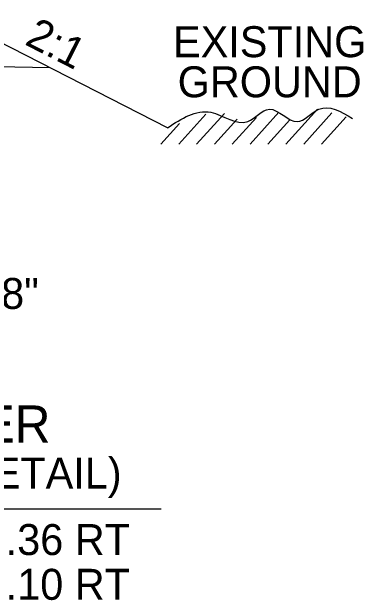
# Model space of a CAD drawing. Extents: x 1553884 to 1554215, y 810431 to 810779.
# Drawn here: x 1554057.23 to 1554068.58, y 810651.68 to 810670.68 of the extents above; entities that cross this region are included whole.
import ezdxf

# ---------------------------------------------------------------- set-up
doc = ezdxf.new("R2010")
doc.units = 0
for name, color, linetype in [('Old_Level_1', 7, 'Continuous'), ('Prop CMT Steel Beam Girder', 7, 'Continuous'), ('Typical Arrow Superelevation CELL', 7, 'Continuous'), ('Typical Shoulder Slope CELL', 7, 'Continuous')]:
    doc.layers.add(name, color=color, linetype=linetype)

msp = doc.modelspace()

# ---------------------------------------------------------------- linework, layer by layer
at = {"layer": 'Old_Level_1'}
for p, q in [((1554062.264, 810666.94), (1554054.916, 810670.684)), ((1554058.463, 810668.877), (1554036.949, 810669.189))]:
    msp.add_line(p, q, dxfattribs=at)
at = {"layer": 'Typical Arrow Superelevation CELL'}
msp.add_line((1554034.791, 810654.636), (1554062.057, 810654.636), dxfattribs=at)
at = {"layer": 'Typical Shoulder Slope CELL'}
for p, q in [((1554067.103, 810667.545), (1554066.082, 810666.41)), ((1554063.5, 810667.382), (1554062.626, 810666.41)), ((1554064.096, 810667.403), (1554063.202, 810666.41)), ((1554065.13, 810667.272), (1554064.354, 810666.41)), ((1554065.855, 810667.438), (1554064.93, 810666.41)), ((1554067.569, 810667.422), (1554066.658, 810666.41)), ((1554068.031, 810667.296), (1554067.234, 810666.41)), ((1554062.651, 810667.078), (1554062.05, 810666.41)), ((1554064.506, 810667.219), (1554063.778, 810666.41)), ((1554066.216, 810667.199), (1554065.506, 810666.41))]:
    msp.add_line(p, q, dxfattribs=at)
msp.add_spline([(1554062.264, 810666.94), (1554063.659, 810667.438), (1554064.854, 810667.139), (1554065.551, 810667.538), (1554066.447, 810667.139), (1554067.144, 810667.538), (1554068.24, 810667.239)], degree=3, dxfattribs=at)

# ---------------------------------------------------------------- texts
at = {"layer": 'Old_Level_1'}
msp.add_text('2:1', height=1, rotation=333, dxfattribs=at).set_placement((1554057.616, 810669.644))
for s, height, p in [('WIDTH VARIES 1\'-8" TO 2\'-8"', 1, (1554040.151, 810661.09)), ('SHOULDER BERM GUTTER', 1.2, (1554037.442, 810656.774))]:
    msp.add_text(s, height=height, dxfattribs=at).set_placement(p)
at = {"layer": 'Prop CMT Steel Beam Girder'}
for s, p in [('(NOTE: SCALE ENLARGED FOR DETAIL)', (1554035.07, 810655.291)), ('-L- STA 18+30.00 TO -L- STA 18+42.36 RT', (1554035.109, 810653.144)), ('-L- STA 21+28.92 TO -L- STA 22+75.10 RT', (1554035.109, 810651.699))]:
    msp.add_text(s, height=1, dxfattribs=at).set_placement(p)
at = {"layer": 'Typical Arrow Superelevation CELL'}
for s, p in [('EXISTING', (1554062.44, 810669.218)), ('GROUND', (1554062.589, 810667.923))]:
    msp.add_text(s, height=1, dxfattribs=at).set_placement(p)

doc.saveas('drawing.dxf')
